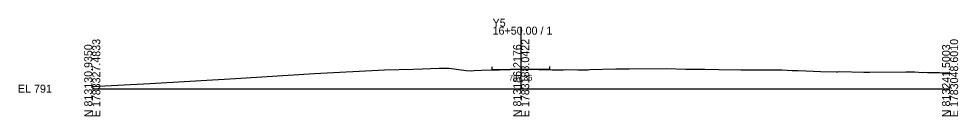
# Model space of a CAD drawing. Extents: x -26 to 1603, y -10 to 6526.
# Drawn here: x 1274.3 to 1602.8, y 3490.3 to 3524.6 of the extents above; entities that cross this region are included whole.
import ezdxf

# ---------------------------------------------------------------- set-up
doc = ezdxf.new("R2010")
doc.units = 0
for name, color, linetype in [('Exist Cross Section Cell', 7, 'Continuous'), ('Exist XS Center Line Elevation Label', 7, 'Continuous'), ('Exist XS Ground Line', 7, 'Continuous'), ('Prop XS EOT Tick Mark', 7, 'Continuous'), ('Prop XS Finish Grade Pavement', 7, 'Continuous')]:
    doc.layers.add(name, color=color, linetype=linetype)

msp = doc.modelspace()

# ---------------------------------------------------------------- linework, layer by layer
at = {"layer": 'Exist Cross Section Cell'}
for p, q in [((1450, 3500), (1450, 3521.79)), ((1300, 3500), (1450, 3500)), ((1450, 3500), (1600, 3500))]:
    msp.add_line(p, q, dxfattribs=at)
at = {"layer": 'Exist XS Ground Line'}
for p, q in [((1377.77, 3505.36), (1402.17, 3506.63)), ((1402.17, 3506.63), (1412.35, 3506.88)), ((1412.35, 3506.88), (1421.35, 3507.26)), ((1421.35, 3507.26), (1424.84, 3507.26)), ((1424.84, 3507.26), (1430.8, 3506.44)), ((1430.8, 3506.44), (1432.68, 3506.33)), ((1432.68, 3506.33), (1433.51, 3506.35)), ((1433.51, 3506.35), (1436.24, 3506.48)), ((1436.24, 3506.48), (1439.9, 3506.59)), ((1439.9, 3506.59), (1442.37, 3506.66)), ((1442.37, 3506.66), (1450.17, 3506.86)), ((1450.17, 3506.86), (1456.14, 3506.77)), ((1456.14, 3506.77), (1460.03, 3506.7)), ((1460.03, 3506.7), (1460.83, 3506.66)), ((1460.83, 3506.66), (1464.84, 3506.68)), ((1464.84, 3506.68), (1465.9, 3506.74)), ((1465.9, 3506.74), (1469.81, 3506.67)), ((1469.81, 3506.67), (1471.25, 3506.66)), ((1471.25, 3506.66), (1473.42, 3506.65)), ((1473.42, 3506.65), (1473.9, 3506.7)), ((1473.9, 3506.7), (1483.06, 3506.95)), ((1483.06, 3506.95), (1484.01, 3506.95)), ((1484.01, 3506.95), (1487.71, 3506.94)), ((1487.71, 3506.94), (1500.94, 3507.1)), ((1500.94, 3507.1), (1507.57, 3506.88)), ((1507.57, 3506.88), (1512.19, 3506.89)), ((1512.19, 3506.89), (1514.18, 3506.85)), ((1514.18, 3506.85), (1519.1, 3506.76)), ((1519.1, 3506.76), (1526.79, 3506.64)), ((1526.79, 3506.64), (1527.91, 3506.62)), ((1527.91, 3506.62), (1535.63, 3506.68)), ((1535.63, 3506.68), (1539.36, 3506.64)), ((1539.36, 3506.64), (1541.3, 3506.6)), ((1541.3, 3506.6), (1543.02, 3506.53)), ((1543.02, 3506.53), (1544.72, 3506.43)), ((1544.72, 3506.43), (1546.85, 3506.43)), ((1546.85, 3506.43), (1549.51, 3506.23)), ((1549.51, 3506.23), (1554.73, 3505.99)), ((1554.73, 3505.99), (1560.33, 3505.96)), ((1560.33, 3505.96), (1560.69, 3505.97)), ((1560.69, 3505.97), (1561.31, 3505.99)), ((1561.31, 3505.99), (1569.79, 3505.86)), ((1569.79, 3505.86), (1571.82, 3505.84)), ((1571.82, 3505.84), (1584.5, 3505.93)), ((1584.5, 3505.93), (1587.57, 3505.95)), ((1587.57, 3505.95), (1590.48, 3505.74)), ((1590.48, 3505.74), (1591.04, 3505.78)), ((1591.04, 3505.78), (1592.09, 3505.69)), ((1592.09, 3505.69), (1592.75, 3505.68)), ((1592.75, 3505.68), (1595.35, 3505.68)), ((1595.35, 3505.68), (1596.29, 3505.68)), ((1596.29, 3505.68), (1598.83, 3505.63)), ((1598.83, 3505.63), (1600, 3505.62)), ((1320.14, 3501.85), (1350.04, 3503.62)), ((1350.04, 3503.62), (1377.77, 3505.36)), ((1300, 3500.8), (1320.14, 3501.85))]:
    msp.add_line(p, q, dxfattribs=at)
at = {"layer": 'Prop XS EOT Tick Mark'}
for p, q in [((1439.86, 3506.71), (1439.86, 3507.71)), ((1460.03, 3506.83), (1460.03, 3507.83))]:
    msp.add_line(p, q, dxfattribs=at)
at = {"layer": 'Prop XS Finish Grade Pavement'}
for p, q in [((1439.86, 3506.71), (1442.37, 3506.79)), ((1442.37, 3506.79), (1450.17, 3506.99)), ((1450.18, 3506.99), (1456.14, 3506.89)), ((1456.14, 3506.89), (1460.03, 3506.83))]:
    msp.add_line(p, q, dxfattribs=at)

# ---------------------------------------------------------------- texts
at = {"layer": 'Exist Cross Section Cell'}
for s, p in [('Y5', (1440, 3521.79)), ('16+50.00 / 1', (1440, 3518.99)), ('EL 791', (1274, 3498.6))]:
    msp.add_text(s, height=2.8, dxfattribs=at).set_placement(p)
for s, p in [('N 813130.9350', (1300, 3490)), ('E 1783327.4833', (1302.8, 3490)), ('N 813186.2176', (1450, 3490)), ('E 1783188.0422', (1452.8, 3490)), ('N 813241.5003', (1600, 3490)), ('E 1783048.6010', (1602.8, 3490))]:
    msp.add_text(s, height=2.8, rotation=90, dxfattribs=at).set_placement(p)
at = {"layer": 'Exist XS Center Line Elevation Label'}
msp.add_text('797.86', height=2, dxfattribs=at).set_placement((1445.73, 3502.86))

doc.saveas('drawing.dxf')
